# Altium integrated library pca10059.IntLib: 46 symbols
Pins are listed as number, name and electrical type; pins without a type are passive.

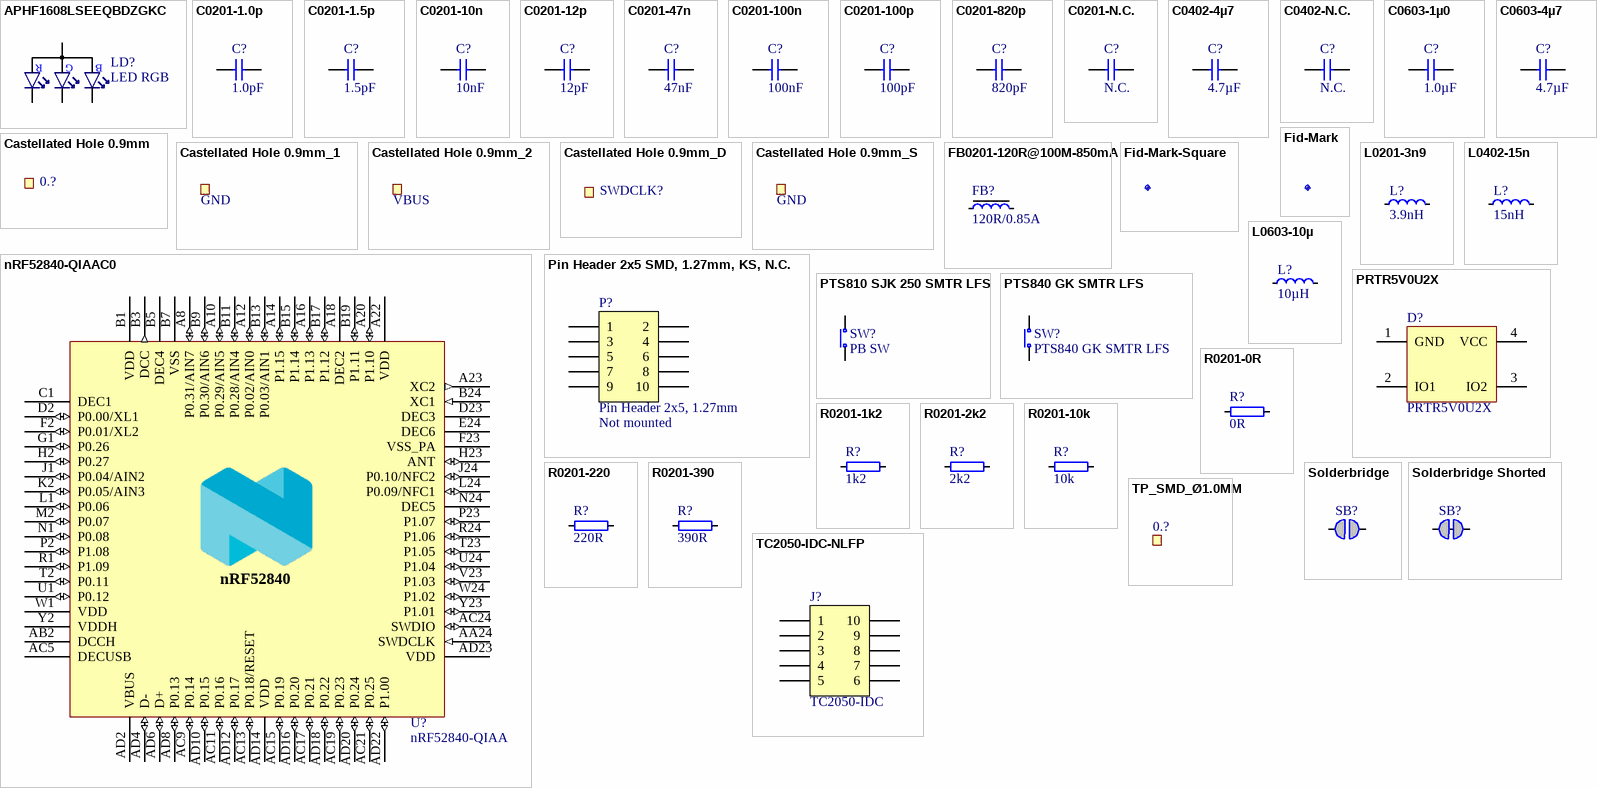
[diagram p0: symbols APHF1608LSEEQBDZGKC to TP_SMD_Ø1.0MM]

## APHF1608LSEEQBDZGKC
designator LD?, comment LED RGB
RGB LED 1.60 mm x 0.80 mm SMD; Part Number: APHF1608LSEEQBDZGKC; Manufacturer: Kingbright Company LLC; Part number IPS: 00000001254; Artikkelnr Noca: N.A.
footprint LED_RGB_0603
pins: 1 C_RED, 2 C_GREEN, 3 C_BLUE, 4 A

## C0201-1.0p
designator C?, comment 1.0pF
Capacitor, NP0, ±5%; Part Number: C0201-1.0p; Part number IPS: 00000001247; Note: 50V; Artikkelnr Noca: N.A.
footprint CAPC0603X03L_C
pins: 1, 2

## C0201-1.5p
designator C?, comment 1.5pF
Capacitor, NP0, ±0.1pF; Part Number: C0201-1.5p; Part number IPS: 00000007107; Note: 50V; Artikkelnr Noca: N.A.
footprint CAPC0603X03L_C
pins: 1, 2

## C0201-10n
designator C?, comment 10nF
Capacitor, X7R, ±10%; Part Number: C0201-10n; Part number IPS: 00000003480; Note: 10V; Artikkelnr Noca: N.A.
footprint CAPC0603X03L_C
pins: 1, 2

## C0201-12p
designator C?, comment 12pF
Capacitor, NP0, ±2%; Part Number: C0201-12p; Part number IPS: 00000007848; Note: 25V; Artikkelnr Noca: N.A.
footprint CAPC0603X03L_C
pins: 1, 2

## C0201-47n
designator C?, comment 47nF
Capacitor, X5R, ±10%; Part Number: C0201-47n; Part number IPS: 00000001250; Note: 10V; Artikkelnr Noca: N.A.
footprint CAPC0603X03L_C
pins: 1, 2

## C0201-100n
designator C?, comment 100nF
Capacitor, X5R, ±10%; Part Number: C0201-100n; Part number IPS: 00000001248; Note: 16V; Artikkelnr Noca: N.A.
footprint CAPC0603X03L_C
pins: 1, 2

## C0201-100p
designator C?, comment 100pF
Capacitor, NP0, ±2%; Part Number: C0201-100p; Part number IPS: 00000007853; Note: 25V; Artikkelnr Noca: N.A.
footprint CAPC0603X03L_C
pins: 1, 2

## C0201-820p
designator C?, comment 820pF
Capacitor, X7R, ±10%; Part Number: C0201-820p; Part number IPS: 00000001249; Note: 25V; Artikkelnr Noca: N.A.
footprint CAPC0603X03L_C
pins: 1, 2

## C0201-N.C.
designator C?, comment N.C.
Not mounted; Part Number: C0201-N.C.; Note: Chip Cap; Artikkelnr Noca: N.A.; Assembly: Not mounted
footprint CAPC0603X03L_C
pins: 1, 2

## C0402-4µ7
designator C?, comment 4.7µF
Capacitor, X5R, ±20%; Part Number: C0402-4µ7; Part number IPS: 00000001251; Note: 10V; Artikkelnr Noca: 20039482; Artikkelnr Simpro: N.A.
footprint CAPC1005X04L
pins: 1, 2

## C0402-N.C.
designator C?, comment N.C.
Not mounted; Part Number: C0402-N.C.; Assembly: Not mounted; Note: Chip Cap; Artikkelnr Noca: N.A.
footprint CAPC1005X04L
pins: 1, 2

## C0603-1µ0
designator C?, comment 1.0µF
Capacitor, X7R, ±10%; Part Number: C0603-1µ0; Part number IPS: 00000000616; Note: 16V; Artikkelnr Noca: 20039335; Artikkelnr Simpro: N.A.
footprint CAPC1608X06L
pins: 1, 2

## C0603-4µ7
designator C?, comment 4.7µF
Capacitor, X5R, ±10%; Part Number: C0603-4µ7; Part number IPS: 00000007783; Note: 6.3V; Artikkelnr Noca: 20069060; Artikkelnr Simpro: N.A.
footprint CAPC1608X06L
pins: 1, 2

## Castellated Hole 0.9mm
designator 0.?, comment CH  (value not drawn)  (no BOM)
Castellated Hole 0.9mm; Artikkelnr Noca: N.A.
footprint Castellated_Hole_0.9mm
pins: 1

## Castellated Hole 0.9mm_1
designator GND?, comment GND  (no BOM)
Castellated Hole 0.9mm; Artikkelnr Noca: N.A.
footprint Castellated_Hole_0.9mm
pins: 1

## Castellated Hole 0.9mm_2
designator VBUS?, comment VBUS  (no BOM)
Castellated Hole 0.9mm; Artikkelnr Noca: N.A.
footprint Castellated_Hole_0.9mm
pins: 1

## Castellated Hole 0.9mm_D
designator SWDCLK?, comment CH  (value not drawn)  (no BOM)
Castellated Hole 0.9mm; Part Number: Castellated Hole 0.9mm_D; Artikkelnr Noca: N.A.
footprint Castellated_Hole_0.9mm_D
pins: 1

## Castellated Hole 0.9mm_S
designator GND?, comment GND  (no BOM)
Castellated Hole 0.9mm; Part Number: Castellated Hole 0.9mm_S; Artikkelnr Noca: N.A.
footprint Castellated_Hole_0.9mm_S
pins: 1

## FB0201-120R@100M-850mA
designator FB?, comment 120R/0.85A
Ferrite Bead, 120 Ohm @ 100MHz, 850mA, 150 mOhm Max; Part Number: FB0201-120R@100M-850mA; Manufacturer: Taiyo Yuden; Manufacturer Part Number: BKP0603HS121-T; Part number IPS: 00000001252; Note: Chip EMIFIL Inductor Type Chip Ferrite Bead; Artikkelnr Noca: N.A.
footprint INDC0603X03L_C
pins: 1, 2

## Fid-Mark
designator Fid?, comment Fiducial mark  (value not drawn)
Part Number: Fid-Mark; Artikkelnr Noca: N.A.
footprint Fiducial

## Fid-Mark-Square
designator Fid?, comment Fiducial mark  (value not drawn)
Part Number: Fid-Mark-Square; Artikkelnr Noca: N.A.
footprint Fiducial_Square

## L0201-3n9
designator L?, comment 3.9nH
Inductor, 400mA, ±0.1nH; Part Number: L0201-3n9; Part number IPS: 00000001253; Note: High frequency chip inductor ±5%; Artikkelnr Noca: N.A.
footprint INDC0603X03L_C
pins: 1, 2

## L0402-15n
designator L?, comment 15nH
Inductor, 320mA, ±5%; Part Number: L0402-15n; Manufacturer: Taiyo Yuden; Manufacturer Part Number: HK100515NJ-T; 2nd source part number: 658-1328; Part number IPS: 00000001262; Note: High frequency chip inductor ±10%; Artikkelnr Noca: 33029323; Artikkelnr Simpro: N.A.
footprint INDC1005X04L
pins: 1, 2

## L0603-10µ
designator L?, comment 10µH
Inductor, 80mA, ±10%; Part Number: L0603-10µ; Manufacturer: Taiyo Yuden; Manufacturer Part Number: LBMF1608T100K; 2nd source part number: 178-6105; Part number IPS: 00000007794; Note: LBMF1608T100K 10µH 80mA 0603; Artikkelnr Noca: 33029314; Artikkelnr Simpro: N.A.
footprint INDC1608X06L
pins: 1, 2

## nRF52840-QIAAC0
designator U?, comment nRF52840-QIAA
Multi-protocol Bluetooth Low Energy, IEEE 802.15.4, ANT and 2.4GHz proprietary system-on-chip; Part Number: nRF52840-QIAAC0; Manufacturer: Nordic Semiconductor; Artikkelnr Noca: 15079380; Artikkelnr Simpro: N.A.
footprint AQFN50P700X700X85_HS-74N
pins: 74 GND (power) hidden to GND, A8 P0.31/AIN7 (io), A10 P0.29/AIN5 (io), A12 P0.02/AIN0 (io), A14 P1.15 (io), A16 P1.13 (io), A18 DEC2 (power), A20 P1.10 (io), A22 VDD (power), A23 XC2 (out), AA24 SWDCLK (in), AB2 DCCH (power), AC5 DECUSB (power), AC9 P0.14 (io), AC11 P0.16 (io), AC13 P0.18/RESET (io), AC15 P0.19 (io), AC17 P0.21 (io), AC19 P0.23 (io), AC21 P0.25 (io), AC24 SWDIO (io), AD2 VBUS (power), AD4 D- (io), AD6 D+ (io), AD8 P0.13 (io), AD10 P0.15 (io), AD12 P0.17 (io), AD14 VDD (power), AD16 P0.20 (io), AD18 P0.22 (io), AD20 P0.24 (io), AD22 P1.00 (io), AD23 VDD (power), B1 VDD (power), B3 DCC (out), B5 DEC4 (power), B7 VSS (power), B9 P0.30/AIN6 (io), B11 P0.28/AIN4 (io), B13 P0.03/AIN1 (io), B15 P1.14 (io), B17 P1.12 (io), B19 P1.11 (io), B24 XC1 (in), C1 DEC1 (power), D2 P0.00/XL1 (io), D23 DEC3 (power), E24 DEC6 (power), F2 P0.01/XL2 (io), F23 VSS_PA (power), G1 P0.26 (io), H2 P0.27 (io), H23 ANT (io), J1 P0.04/AIN2 (io), J24 P0.10/NFC2 (io), K2 P0.05/AIN3 (io), L1 P0.06 (io), L24 P0.09/NFC1 (io), M2 P0.07 (io), N1 P0.08 (io), N24 DEC5 (power), P2 P1.08 (io), P23 P1.07 (io), R1 P1.09 (io), R24 P1.06 (io), T2 P0.11 (io), T23 P1.05 (io), U1 P0.12 (io), U24 P1.04 (io), V23 P1.03 (io), W1 VDD (power), W24 P1.02 (io), Y2 VDDH (power), Y23 P1.01 (io)

## Pin Header 2x5 SMD, 1.27mm, KS, N.C.
designator P?, comment Pin Header 2x5, 1.27mm  Assembly: Not mounted
Pin Header 2x5, 1.27mm (50mil), SMD, Keying Shroud; Part Number: Pin Header 2x5 SMD, 1.27mm, KS, N.C.; Manufacturer: W-CON; Manufacturer Part Number: 3132-10MS0BK00R1; 2nd source part number: FTSH-105-01-F-DV-K; Artikkelnr Noca: N.A.
footprint HDR_2x5-SMD-1.27mm-NC
pins: 1, 2, 3, 4, 5, 6, 7, 8, 9, 10

## PRTR5V0U2X
designator D?
Ultra low capacitance double rail-to-rail ESD protection diode; Manufacturer: NXP; 2nd source part number: 152-4157; Part number IPS: 00000009951; Artikkelnr Noca: 10069015; Artikkelnr Simpro: N.A.
footprint SOT190P230X110-4L
pins: 1 GND, 2 IO1, 3 IO2, 4 VCC

## PTS810 SJK 250 SMTR LFS
designator SW?, comment PB SW
Tactile Switch, SPNO, SMD, 260gf, 4.2x3.2x2.5mm; Part Number: PTS810 SJK 250 SMTR LFS; Manufacturer: C&K Components; Part number IPS: 00000001259; Artikkelnr Noca: N.A.
footprint C&K_PTS810
pins: 1 N.O, 2 COM

## PTS840 GK SMTR LFS
designator SW?
Microminiature SMT Switch, Side Actuated; Manufacturer: C&K Components; 2nd source part number: 611-PTS840GKSMTR; Part number IPS: 00000001260; Note: Tactile Switch, SPST, SMD, 220gf; Artikkelnr Noca: 50019089; Artikkelnr Simpro: N.A.
footprint EVQP7A/J/B/K
pins: 1 N.O, 2 COM

## R0201-0R
designator R?, comment 0R
Resistor, ±5%, 0.05W; Part Number: R0201-0R; Part number IPS: 00000003245; Note: Chip Res 5%; Artikkelnr Noca: N.A.; Value Ohm: 0
footprint RESC0603X03L_C
pins: 1, 2

## R0201-1k2
designator R?, comment 1k2
Resistor, ±1%, 0.05W; Part Number: R0201-1k2; Part number IPS: 00000001256; Note: Chip Res 1%; Artikkelnr Noca: N.A.; Value Ohm: 1200
footprint RESC0603X03L_C
pins: 1, 2

## R0201-2k2
designator R?, comment 2k2
Resistor, ±1%, 0.05W; Part Number: R0201-2k2; Part number IPS: 00000001257; Note: Chip Res 1%; Artikkelnr Noca: N.A.; Value Ohm: 2200
footprint RESC0603X03L_C
pins: 1, 2

## R0201-10k
designator R?, comment 10k
Resistor, ±1%, 0.05W; Part Number: R0201-10k; Part number IPS: 00000001255; Note: Chip Res 1%; Artikkelnr Noca: N.A.; Value Ohm: 10000
footprint RESC0603X03L_C
pins: 1, 2

## R0201-220
designator R?, comment 220R
Resistor, ±1%, 0.05W; Part Number: R0201-220; Part number IPS: 00000000863; Note: Chip Res 1%; Artikkelnr Noca: N.A.; Value Ohm: 220
footprint RESC0603X03L_C
pins: 1, 2

## R0201-390
designator R?, comment 390R
Resistor, ±1%, 0.05W; Part Number: R0201-390; Part number IPS: 00000001258; Note: Chip Res 1%; Artikkelnr Noca: N.A.; Value Ohm: 390
footprint RESC0603X03L_C
pins: 1, 2

## Solderbridge
designator SB?  (value not drawn)  (no BOM)
Artikkelnr Noca: N.A.
footprint Solderbridge
pins: 1 0, 2 1

## Solderbridge Shorted
designator SB?, comment Solderbridge  (value not drawn)  (net tie, no BOM)
Shorted Solderbridge; Part Number: Solderbridge Shorted; Artikkelnr Noca: N.A.
footprint Solderbridge_Shorted
pins: 1 0, 2 1

## TC2050-IDC-NLFP
designator J?, comment TC2050-IDC  (no BOM)
CBL PLUG-OF-NAILS 10-PIN; Part Number: TC2050-IDC-NLFP; Manufacturer: Tag-Connect LLC; Artikkelnr Noca: N.A.
footprint TC2050-IDC-NLFP
pins: 1, 2, 3, 4, 5, 6, 7, 8, 9, 10

## TP_SMD_Ø1.0MM
designator 0.?, comment Ø1.0mm,SMD  (value not drawn)  (no BOM)
1.0mm circular SMD testpad; Part Number: TP_SMD_Ø1.0MM; Manufacturer: Nordic Semiconductor; Artikkelnr Noca: N.A.
footprint TP_SMD_Ø1.0mm
pins: 1

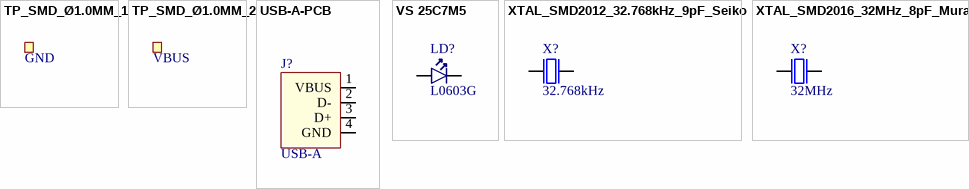
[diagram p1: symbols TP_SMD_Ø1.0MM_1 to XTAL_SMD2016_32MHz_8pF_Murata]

## TP_SMD_Ø1.0MM_1
designator GND?, comment GND  (no BOM)
1.0mm circular SMD testpad; Part Number: TP_SMD_Ø1.0MM; Manufacturer: Nordic Semiconductor; Artikkelnr Noca: N.A.
footprint TP_SMD_Ø1.0mm
pins: 1

## TP_SMD_Ø1.0MM_2
designator VBUS?, comment VBUS  (no BOM)
1.0mm circular SMD testpad; Part Number: TP_SMD_Ø1.0MM; Manufacturer: Nordic Semiconductor; Artikkelnr Noca: N.A.
footprint TP_SMD_Ø1.0mm
pins: 1

## USB-A-PCB
designator J?, comment USB-A  (no BOM)
USB-A PCB footprint; Part Number: USB-A-PCB; Artikkelnr Noca: N.A.
footprint USB-A-PCB
pins: 1 VBUS, 2 D-, 3 D+, 4 GND

## VS 25C7M5
designator LD?, comment L0603G
LED, Green, 0603, 573nm, Vf=2.0V, 24mcd, - 40 to +85°C; Part Number: VS 25C7M5; Manufacturer: Victory Electronics; Artikkelnr Noca: N.A.
footprint LED_0603_G
pins: 1 C, 2 A

## XTAL_SMD2012_32.768kHz_9pF_Seiko
designator X?, comment 32.768kHz
XTAL SMD 2012, 32.768kHz, 9pF, ±20ppm; Part Number: XTAL_SMD2012_32.768kHz_9pF_Seiko; Manufacturer: Seiko; Manufacturer Part Number: SC20S-9.0PF20PPM; Part number IPS: 80000001425; Note: XTAL SMD 32.768kHz; Artikkelnr Noca: N.A.
footprint XTAL_2012
pins: 1 inp, 2 out

## XTAL_SMD2016_32MHz_8pF_Murata
designator X?, comment 32MHz
XTAL SMD 2016, 32MHz, Cl=8pF, Tol: ±10ppm, Stab: ±10ppm; Part Number: XTAL_SMD2016_32MHz_8pF_Murata; Manufacturer: Murata; Manufacturer Part Number: XRCGB32M000F1H01R0; Part number IPS: 80000001424; Note: XTAL SMD 32.000MHz; Artikkelnr Noca: N.A.
footprint BT-XTAL_2016
pins: 1 inp, 2 GND hidden to GND, 3 out, 4 GND hidden to GND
